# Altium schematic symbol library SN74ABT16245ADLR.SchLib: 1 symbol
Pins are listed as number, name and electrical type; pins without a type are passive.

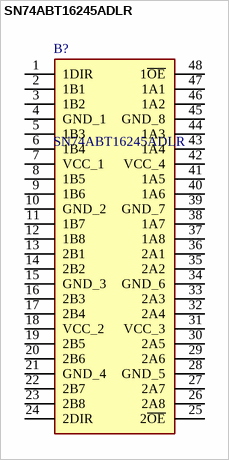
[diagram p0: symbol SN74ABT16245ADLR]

## SN74ABT16245ADLR
designator B?
Texas Instruments SN74ABT16245ADLR, Dual, Bus Transceiver, 16-Bit Non-Inverting TTL, 5V, 48-Pin SSOP; Geometry.Height: 2.79mm
footprint SOP64P1035X279-48N
pins: 1 1DIR, 2 1B1, 3 1B2, 4 GND_1, 5 1B3, 6 1B4, 7 VCC_1, 8 1B5, 9 1B6, 10 GND_2, 11 1B7, 12 1B8, 13 2B1, 14 2B2, 15 GND_3, 16 2B3, 17 2B4, 18 VCC_2, 19 2B5, 20 2B6, 21 GND_4, 22 2B7, 23 2B8, 24 2DIR, 25 2~{OE}, 26 2A8, 27 2A7, 28 GND_5, 29 2A6, 30 2A5, 31 VCC_3, 32 2A4, 33 2A3, 34 GND_6, 35 2A2, 36 2A1, 37 1A8, 38 1A7, 39 GND_7, 40 1A6, 41 1A5, 42 VCC_4, 43 1A4, 44 1A3, 45 GND_8, 46 1A2, 47 1A1, 48 1~{OE}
